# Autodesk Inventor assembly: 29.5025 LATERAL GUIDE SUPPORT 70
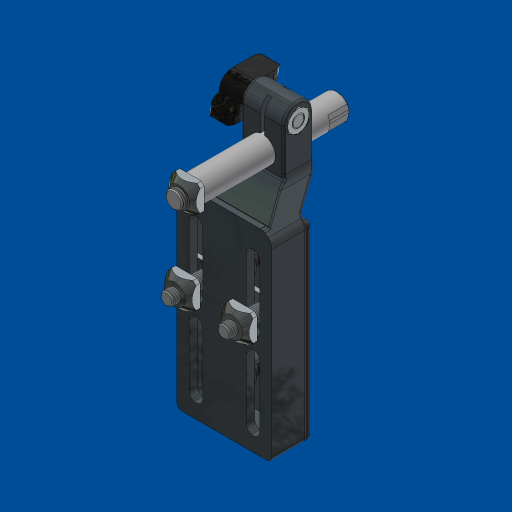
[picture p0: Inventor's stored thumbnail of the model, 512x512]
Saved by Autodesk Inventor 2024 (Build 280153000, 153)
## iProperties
Created: 2007-07
Part Number: 29.5025 LATERAL GUIDE SUPPORT 70
Document SubType Name: Assembly
Designer: Andy Moles
Description: LATERAL GUIDE SUPPORT 140
Author: Andy Moles
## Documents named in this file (11)
- L:\INVENTOR LIBRARIES\PARTS LIBRARY\BELT AND ROLLER CONVEYORS\29.5025 LATERAL GUIDE SUPPORT 70.iam
- L:\INVENTOR LIBRARIES\PARTS LIBRARY\BELT AND ROLLER CONVEYORS\SUBCOMPONENTS\29.5028 LATERAL GUIDE SUPPORT 140 WINGKNOB.ipt
- L:\INVENTOR LIBRARIES\PARTS LIBRARY\FASTENING ELEMENTS\NUTS\21.1525 M6 HEX NUT.ipt
- L:\INVENTOR LIBRARIES\PARTS LIBRARY\FASTENING ELEMENTS\NUTS\21.1351 M8 SQUARE NUT.ipt
- L:\INVENTOR LIBRARIES\PARTS LIBRARY\BELT AND ROLLER CONVEYORS\SUBCOMPONENTS\29.5028 LATERAL GUIDE SUPPORT 140 BODY NEW.ipt
- L:\INVENTOR LIBRARIES\PARTS LIBRARY\FASTENING ELEMENTS\SCREWS CAP\21.1240 M6X20.ipt
- L:\INVENTOR LIBRARIES\PARTS LIBRARY\FASTENING ELEMENTS\WASHERS\21.1363 WASHER M6.ipt
- L:\INVENTOR LIBRARIES\PARTS LIBRARY\FASTENING ELEMENTS\NUTS\21.1330 M6 SQUARE NUT.ipt
- L:\INVENTOR LIBRARIES\PARTS LIBRARY\END CAPS\22.1007_1 END CAP 45x90  GRAY.iam
- 22.1007/1 END CAP 45x90  GRAY.iam
- L:\INVENTOR LIBRARIES\PARTS LIBRARY\BELT AND ROLLER CONVEYORS\SUBCOMPONENTS\29.5025 LATERAL GUIDE SUPPORT 70 ROD.ipt
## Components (12 placed, 9 different names)
1. 29.5028 LATERAL GUIDE SUPPORT 140 BODY NEW:1 — Mate:11, Flush:1, Mate:12, Angle:1, Mate:14, Angle:2, Insert:5, Mate:15, Angle:3, Mate:16, Mate:17, Mate:18, Angle:4, Mate:19, Mate:20, Mate:21, Mate:22, Angle:6, Mate:25, Mate:26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
2. 29.5028 LATERAL GUIDE SUPPORT 140 WINGKNOB:1 — Mate:10, Mate:14, Mate:15, Angle:3
3. 21.1525 M6 HEX NUT:1 — Mate:10, Angle:2, Insert:5
4. 21.1351 M8 SQUARE NUT:2 — Angle:1, Insert:8
5. 21.1240  M6x20 SHCS:1 — Insert:7, Mate:18, Mate:23
6. 21.1240  M6x20 SHCS:2 — Insert:6, Mate:20, Mate:24
7. 21.1363 WASHER M6:1 — Insert:7, Mate:16, Angle:4, Flush:2
8. 21.1363 WASHER M6:2 — Insert:6, Mate:17, Mate:19, Flush:2
9. 21.1330 M6 SQUARE NUT:1 — Mate:21, Mate:23, Angle:5, Angle:6
10. 21.1330 M6 SQUARE NUT:2 — Mate:22, Mate:24, Angle:5
11. 22.1007\1 END CAP 45x90  GRAY:1 [sub-assembly] — Mate:25, Mate:26, Angle:7
12. 29.5025 LATERAL GUIDE SUPPORT 70 ROD:1 — Mate:27, Angle:8, Insert:8
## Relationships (31: Mate 17, Angle 8, Insert 4, Flush 2)
- Mate:10: 29.5028 LATERAL GUIDE SUPPORT 140 WINGKNOB:1 ↔ 21.1525 M6 HEX NUT:1
- Mate:11: 29.5028 LATERAL GUIDE SUPPORT 140 BODY NEW:1
- Flush:1: 29.5028 LATERAL GUIDE SUPPORT 140 BODY NEW:1
- Mate:12: 29.5028 LATERAL GUIDE SUPPORT 140 BODY NEW:1
- Angle:1: 29.5028 LATERAL GUIDE SUPPORT 140 BODY NEW:1 ↔ 21.1351 M8 SQUARE NUT:2
- Mate:14: 29.5028 LATERAL GUIDE SUPPORT 140 BODY NEW:1 ↔ 29.5028 LATERAL GUIDE SUPPORT 140 WINGKNOB:1
- Angle:2: 29.5028 LATERAL GUIDE SUPPORT 140 BODY NEW:1 ↔ 21.1525 M6 HEX NUT:1
- Insert:5: 29.5028 LATERAL GUIDE SUPPORT 140 BODY NEW:1 ↔ 21.1525 M6 HEX NUT:1
- Mate:15: 29.5028 LATERAL GUIDE SUPPORT 140 BODY NEW:1 ↔ 29.5028 LATERAL GUIDE SUPPORT 140 WINGKNOB:1
- Angle:3: 29.5028 LATERAL GUIDE SUPPORT 140 BODY NEW:1 ↔ 29.5028 LATERAL GUIDE SUPPORT 140 WINGKNOB:1
- Insert:6: 21.1240  M6x20 SHCS:2 ↔ 21.1363 WASHER M6:2
- Insert:7: 21.1240  M6x20 SHCS:1 ↔ 21.1363 WASHER M6:1
- Mate:16: 29.5028 LATERAL GUIDE SUPPORT 140 BODY NEW:1 ↔ 21.1363 WASHER M6:1
- Mate:17: 29.5028 LATERAL GUIDE SUPPORT 140 BODY NEW:1 ↔ 21.1363 WASHER M6:2
- Mate:18: 29.5028 LATERAL GUIDE SUPPORT 140 BODY NEW:1 ↔ 21.1240  M6x20 SHCS:1
- Angle:4: 29.5028 LATERAL GUIDE SUPPORT 140 BODY NEW:1 ↔ 21.1363 WASHER M6:1
- Mate:19: 29.5028 LATERAL GUIDE SUPPORT 140 BODY NEW:1 ↔ 21.1363 WASHER M6:2
- Mate:20: 29.5028 LATERAL GUIDE SUPPORT 140 BODY NEW:1 ↔ 21.1240  M6x20 SHCS:2
- Flush:2: 21.1363 WASHER M6:1 ↔ 21.1363 WASHER M6:2
- Mate:21: 29.5028 LATERAL GUIDE SUPPORT 140 BODY NEW:1 ↔ 21.1330 M6 SQUARE NUT:1
- Mate:22: 29.5028 LATERAL GUIDE SUPPORT 140 BODY NEW:1 ↔ 21.1330 M6 SQUARE NUT:2
- Mate:23: 21.1240  M6x20 SHCS:1 ↔ 21.1330 M6 SQUARE NUT:1
- Mate:24: 21.1240  M6x20 SHCS:2 ↔ 21.1330 M6 SQUARE NUT:2
- Angle:5: 21.1330 M6 SQUARE NUT:1 ↔ 21.1330 M6 SQUARE NUT:2
- Angle:6: 29.5028 LATERAL GUIDE SUPPORT 140 BODY NEW:1 ↔ 21.1330 M6 SQUARE NUT:1
- Mate:25: 29.5028 LATERAL GUIDE SUPPORT 140 BODY NEW:1 ↔ 22.1007\1 END CAP 45x90  GRAY:1
- Mate:26: 29.5028 LATERAL GUIDE SUPPORT 140 BODY NEW:1 ↔ 22.1007\1 END CAP 45x90  GRAY:1
- Angle:7: 29.5028 LATERAL GUIDE SUPPORT 140 BODY NEW:1 ↔ 22.1007\1 END CAP 45x90  GRAY:1
- Mate:27: 29.5028 LATERAL GUIDE SUPPORT 140 BODY NEW:1 ↔ 29.5025 LATERAL GUIDE SUPPORT 70 ROD:1
- Angle:8: 29.5028 LATERAL GUIDE SUPPORT 140 BODY NEW:1 ↔ 29.5025 LATERAL GUIDE SUPPORT 70 ROD:1
- Insert:8: 21.1351 M8 SQUARE NUT:2 ↔ 29.5025 LATERAL GUIDE SUPPORT 70 ROD:1
